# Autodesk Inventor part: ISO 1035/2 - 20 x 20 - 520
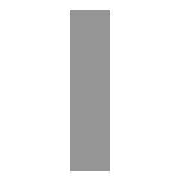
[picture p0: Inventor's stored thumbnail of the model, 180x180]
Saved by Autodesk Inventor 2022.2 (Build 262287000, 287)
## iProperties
_CCFamilyMember: 168
_CCFamilyDisplayName: ISO 1035/2 - 1980 - Barre in acciaio laminate a caldo - Parte 2: barre quadre
_FrameMemberDoc: Frame Member File
_Version: 25.0.0
_GetPNFromCC: 1
Created: 2025-02
Part Number: ISO 1035/2 - 20 x 20 - 520
Material: Acciaio, Dolce
Description: Barre in acciaio laminate a caldo - Parte 2: barre quadre
Document SubType Name: Modeling
Standard: ISO 1035/2
Designer: 18907419
Standard Revision: First edition 1980-10-15
Standards Organization: ISO
Language: it-IT
Size Designation: 20x 20
Categories: <MemberInstance><Categories><Category DisplayName="Forme strutturali" InternalName="089c4875-fa83-4c05-b084-43b9cc11f5ed" Mnemonic="GRDR"><CategoryParameter Dis
Stock Number: 20x 20
Density: 7.85 g/cm^3
Appearance: Semilucidato
IsCustomPart: 1
G_L: 520,000 mm
G_W: 20,000 mm
G_H: 20,000 mm
+D4C4440D-AAA4-41A5-A4A6-87245F75C31E+CUTDETAIL1: Angolo retto 45,00 gr
+3A27C3CC-6522-4282-AD02-8628071835D6+CUTDETAIL2: Angolo retto 45,00 gr
+AEBD2E9C-AE8F-4A22-BA5A-C394ECEA898C+CUTDETAIL3: Angolo retto 45,00 gr
+735E3BF1-8EBF-4594-9FF7-BC9BC0BA5294+CUTDETAIL4: Angolo retto 45,00 gr
Author: 18907419
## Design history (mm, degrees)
node "Piano iniziale"
node "Piano finale"
sketch "Schizzo"
  geometry: L1 (10, -10)-(-10, -10); L2 (-10, -10)-(-10, 10); L3 (-10, 10)-(10, 10); L4 (10, 10)-(10, -10); L5 (-6, 0)-(8, 0); L6 (0, -30)-(0, 40); L7 (0, 54)-(0, -44) reference; L8 (-14, 0)-(14, 0) reference
  constraints: 12 end point, 2 collinear, 2 parallel, 1 horizontal, 1 perpendicular
  dimensions: "d0" = 20 distance between parallel lines of L3 L1 (= G_W); "d1" = 20 distance between parallel lines of L4 L2 (= G_H); "d4" = 10 distance between parallel lines of L6 L4 (= 0.5 x d1); "d5" = 10 distance between parallel lines of L5 L3 (= 0.5 x d0)
extrude "Corpo" new body sketch "Schizzo" stored distance "d2" = 520 (= G_L); taper "d3" = 0 deg
node "Driven Length"
  sketch "Sketch3"
    geometry: L1 (0, 0)-(10, 0) reference
    constraints: 2 end point, 1 horizontal
  workplane "Work Plane3"
  sketch "Sketch4"
    geometry: L1 (-2, -10)-(12, -10) reference; L2 (-2, 510)-(12, 510) reference
    dimensions: "d9" = 520 dimension on L1 L2 (derived)
node "Piano di lavoro4"
feature "Divisione1"
node "Piano di lavoro5"
feature "Divisione2"
node "Piano di lavoro6"
feature "Divisione3"
node "Piano di lavoro7"
feature "Divisione4"
body "Solid1"
other parameters: "G_W" = 20 [user parameter; used in 1 equation term], "G_H" = 20 [user parameter; used in 1 equation term], "G_L" = 520 (= d9) [user parameter; used in 1 equation term], "d8" = 90 deg
